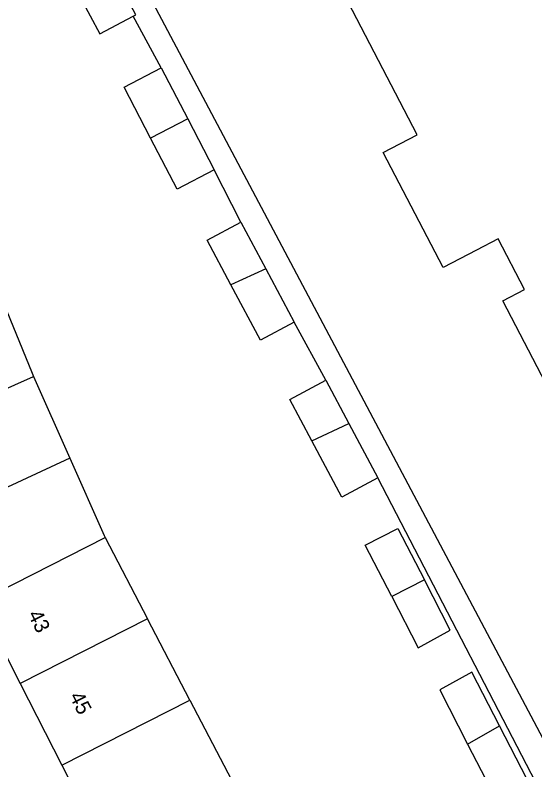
# Model space of a CAD drawing. Extents: x 162074 to 163034, y 381824 to 382557.
# Drawn here: x 162526.5 to 162561.2, y 382342.2 to 382392.7 of the extents above; entities that cross this region are included whole.
import ezdxf

# ---------------------------------------------------------------- set-up
doc = ezdxf.new("R2010")
doc.units = 0
for name, color, linetype in [('IMGEO_Pand', 7, 'Continuous'), ('IMGEO_Pand_nummerreeks', 7, 'Continuous'), ('IMGEO_Voetpad_open', 7, 'Continuous')]:
    doc.layers.add(name, color=color, linetype=linetype)

msp = doc.modelspace()

# ---------------------------------------------------------------- linework, layer by layer
at = {"layer": 'IMGEO_Pand'}
for points in [[(162570.821, 382350.911), (162559.051, 382373.589), (162560.496, 382374.339), (162558.734, 382377.733), (162557.289, 382376.983), (162555.051, 382375.822), (162551.058, 382383.517), (162553.32, 382384.692), (162545.561, 382399.659), (162563.063, 382408.737)], [(162534.354, 382392.613), (162534.54, 382392.712), (162532.619, 382396.316)], [(162530.193, 382395.078), (162532.136, 382391.431), (162534.354, 382392.613)], [(162535.519, 382384.464), (162533.749, 382387.873), (162536.229, 382389.161)], [(162536.229, 382389.161), (162538, 382385.752)], [(162538, 382385.752), (162535.519, 382384.464)], [(162538, 382385.752), (162539.771, 382382.342)], [(162539.771, 382382.342), (162537.29, 382381.054), (162535.519, 382384.464)], [(162540.884, 382374.655), (162539.287, 382377.639), (162541.538, 382378.845)], [(162541.538, 382378.845), (162543.205, 382375.731)], [(162543.205, 382375.731), (162540.884, 382374.655)], [(162543.205, 382375.731), (162545.112, 382372.169)], [(162545.112, 382372.169), (162542.86, 382370.963), (162540.884, 382374.655)], [(162525.46, 382373.988), (162527.606, 382368.746), (162527.698, 382368.537)], [(162518.95, 382364.628), (162527.698, 382368.537)], [(162527.698, 382368.537), (162530.113, 382363.078)], [(162546.282, 382364.23), (162544.81, 382366.993), (162547.214, 382368.274)], [(162547.214, 382368.274), (162548.752, 382365.387)], [(162546.282, 382364.23), (162548.752, 382365.387)], [(162548.752, 382365.387), (162550.694, 382361.743)], [(162550.694, 382361.743), (162548.29, 382360.462), (162546.282, 382364.23)], [(162530.113, 382363.078), (162521.438, 382359.026)], [(162530.113, 382363.078), (162532.409, 382357.888), (162532.479, 382357.754)], [(162551.621, 382353.819), (162549.856, 382357.256), (162552.037, 382358.376), (162553.802, 382354.939)], [(162524.032, 382353.472), (162532.479, 382357.754)], [(162532.479, 382357.754), (162535.309, 382352.316)], [(162553.802, 382354.939), (162551.621, 382353.819)], [(162551.621, 382353.819), (162553.386, 382350.382), (162555.529, 382351.576), (162553.802, 382354.939)], [(162524.032, 382353.472), (162526.808, 382348.005)], [(162535.309, 382352.316), (162526.808, 382348.005)], [(162538.14, 382346.878), (162535.309, 382352.316)], [(162558.819, 382345.169), (162556.972, 382348.765), (162554.83, 382347.571), (162556.692, 382343.945)], [(162526.808, 382348.005), (162529.583, 382342.539)], [(162529.583, 382342.539), (162538.14, 382346.878)], [(162538.14, 382346.878), (162540.91, 382341.557)], [(162556.692, 382343.945), (162558.819, 382345.169)], [(162556.692, 382343.945), (162558.497, 382340.43), (162560.666, 382341.573), (162558.819, 382345.169)], [(162529.583, 382342.539), (162532.357, 382337.073)]]:
    msp.add_lwpolyline(points, dxfattribs=at)
at = {"layer": 'IMGEO_Voetpad_open'}
for points in [[(162529.011, 382406.096), (162569.932, 382328.823)], [(162536.229, 382389.161), (162534.354, 382392.613)], [(162541.538, 382378.845), (162539.771, 382382.342)], [(162547.214, 382368.274), (162545.112, 382372.169)], [(162563.099, 382337.82), (162550.694, 382361.743)]]:
    msp.add_lwpolyline(points, dxfattribs=at)

# ---------------------------------------------------------------- texts
at = {"layer": 'IMGEO_Pand_nummerreeks'}
for s, p in [('43', (162527.293, 382352.615)), ('45', (162530.068, 382347.149))]:
    msp.add_text(s, height=1, rotation=296.9156, dxfattribs=at).set_placement(p)

doc.saveas('drawing.dxf')
